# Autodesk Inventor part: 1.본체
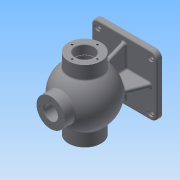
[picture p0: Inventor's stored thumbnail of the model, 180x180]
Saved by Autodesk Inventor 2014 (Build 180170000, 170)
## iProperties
Created: 2017-01
Part Number: 1.본체
Material: Generic
Document SubType Name: Modeling
Designer: ksu
Density: 1 g/cm^3
Appearance: Default
Author: ksu
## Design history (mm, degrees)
sketch "Sketch1"
  geometry: L1 (-62.5, 57.5)-(62.5, 57.5); L2 (62.5, 57.5)-(62.5, -57.5); L3 (62.5, -57.5)-(-62.5, -57.5); L4 (-62.5, -57.5)-(-62.5, 57.5); L5 (-62.5, 57.5)-(62.5, -57.5); L6 (62.5, 57.5)-(-62.5, -57.5); 1 further point
  constraints: 12 end point, 2 midpoint, 2 parallel, 1 horizontal, 1 perpendicular
  dimensions: "d0" = 125 distance of L2.end L3.end; "d1" = 115 distance of L1.end L2.end
extrude "Extrusion1" new body sketch "Sketch1" distance "d2" = 10; taper "d3" = 0 deg
fillet "Fillet1" dims "d4" = 12
fillet "Fillet2" dims "d5" = 3
sketch "Sketch2"
  geometry: A1 r 9 centre (-50.5, 45.5) between (-50.5, 54.5) and (-59.5, 45.5) reference; A2 r 9 centre (-50.5, -45.5) between (-59.5, -45.5) and (-50.5, -54.5) reference; A3 r 9 centre (50.5, -45.5) between (50.5, -54.5) and (59.5, -45.5) reference; A4 r 9 centre (50.5, 45.5) between (59.5, 45.5) and (50.5, 54.5) reference; 5 further points
  constraints: 4 coincident
hole "Hole1" sketch "Sketch2" at (-50.5, 45.5), (-50.5, -45.5), (50.5, -45.5), (50.5, 45.5) diameter "d6" = 8; stored, may be unused: countersink angle "d10" = 90 deg, drill point angle "d12" = 118 deg; dims "d7" = 6, "d8" = 12, "d9" = 3, "d11" = 8
sketch "Sketch3"
  geometry: L1 (-50.5, 0)-(50.5, 0) reference; L2 (0, 150.015)-(0, -20.474); L3 (0, 138)-(0, 32); A1 r 53 centre (0, 85) between (0, 138) and (0, 32); 1 further point
  constraints: 4 end point, 2 point on circle, 2 point on line, 1 centre point, 1 collinear, 1 perpendicular
  dimensions: "d13" = 106 diameter of A1; "d14" = 85 distance from line of L1 A1.centre
revolve "Revolution1" sketch "Sketch3" stored, may be unused: angle "d15" = 90 deg
sketch "Sketch4"
  geometry: L1 (-62.5, 7)-(-62.5, 0) reference; L2 (62.5, 0)-(62.5, 7) reference; L3 (-50.5, 0)-(50.5, 0) reference; C1 r 31 at (0, 85); 1 further point
  constraints: 1 centre point
  dimensions: "d16" = 125 distance between parallel lines of L1 L2 (derived); "d17" = 62 diameter of C1; "d18" = 85 distance from line of L3 C1.centre
extrude "Extrusion2" join sketch "Sketch4" stored distance "d19" = 136; taper "d20" = 0 deg
workplane "Work Plane1"
sketch "Sketch5"
  geometry: C1 r 27 at (0, 0); 1 further point
  constraints: 1 centre point, 1 coincident
  dimensions: "d22" = 54 diameter of C1
extrude "Extrusion3" join sketch "Sketch5" distance "d23" = 65; taper "d24" = 0 deg
sketch "Sketch6"
  geometry: L1 (-59.5, 10)-(-50.5, 10) reference; L2 (50.5, 10)-(-50.5, 10) reference; L3 (50.5, 10)-(59.5, 10) reference; L4 (-50.5, 10)-(50.5, 10) reference; L5 (-52.5, 10)-(-35.28, 52.62); L6 (-62.5, 0)-(-62.5, 7) reference; L7 (52.5, 10)-(35.28, 52.62); L8 (62.5, 7)-(62.5, 0) reference; L9 (-35.28, 52.62)-(35.28, 52.62); L10 (-52.5, 10)-(52.5, 10); 1 further point
  constraints: 8 end point, 2 point on line, 1 collinear, 1 perpendicular
  dimensions: "d25" = 10 distance from line of L6 L5.start; "d26" = 22 deg angle of L6 L5; "d27" = 10 distance from line of L7.start L8; "d28" = 22 deg angle of L7 L8
extrude "Extrusion4" join sketch "Sketch6" stored distance "d29" = 8; taper "d30" = 0 deg
sketch "Sketch7"
  geometry: L1 (-45.5, 10)-(45.5, 10) reference; L2 (-51.5, 10)-(-39.5, 10) reference; L3 (-54.5, 10)-(-45.5, 10) reference; L4 (45.5, 10)-(54.5, 10) reference; L5 (-47.5, 10)-(-31.246, 50.23); L6 (-57.5, 0)-(-57.5, 7) reference; L7 (47.5, 10)-(31.246, 50.23); L8 (57.5, 7)-(57.5, 0) reference; L9 (-31.246, 50.23)-(31.246, 50.23); L10 (-47.5, 10)-(47.5, 10); A1 r 3 centre (-54.5, 7) between (-54.5, 10) and (-57.5, 7) reference; A2 r 3 centre (54.5, 7) between (57.5, 7) and (54.5, 10) reference; 1 further point
  constraints: 8 end point, 2 point on line, 1 collinear, 1 perpendicular
  dimensions: "d31" = 10 distance from line of L6 L5.start; "d32" = 22 deg angle of L6 L5; "d33" = 22 deg angle of L7 L8; "d34" = 10 distance from line of L8 L7.start
extrude "Extrusion5" join sketch "Sketch7" stored distance "d35" = 8; taper "d36" = 0 deg
fillet "Fillet3" dims "d37" = 3
fillet "Fillet4" dims "d38" = 3
fillet "Fillet5" dims "d39" = 3
sketch "Sketch8"
  geometry: L1 (-103.502, 85)-(116.5, 85); L2 (-43, 85)-(43, 85); A1 r 43 centre (0, 85) between (43, 85) and (-43, 85); 1 further point
  constraints: 4 end point, 3 point on line, 2 point on circle, 1 centre point, 1 collinear, 1 horizontal
  dimensions: "d40" = 85 distance from line of point (0, 0) L1; "d41" = 86 diameter of A1
revolve "Revolution2" sketch "Sketch8" stored, may be unused: angle "d42" = 90 deg
sketch "Sketch9"
  geometry: C1 r 31 at (0, 0) reference; C2 r 17.5 at (0, 0); 1 further point
  constraints: 1 centre point, 1 coincident
  dimensions: "d43" = 35 diameter of C2
extrude "Extrusion6" cut sketch "Sketch9" stored distance "d44" = 8; taper "d45" = 0 deg
sketch "Sketch10"
  geometry: L1 (68, 102.5)-(68, 67.5) reference; L2 (-76.217, 85)-(110.893, 85); L3 (52, 85)-(50.25, 85); L4 (50.25, 85)-(50.25, 66.5); L5 (50.25, 66.5)-(52, 66.5); L6 (52, 66.5)-(52, 85); 1 further point
  constraints: 10 end point, 2 parallel, 2 perpendicular, 1 horizontal, 1 point on line
  dimensions: "d46" = 85 distance from line of point (0, 0) L2; "d47" = 16 distance between parallel lines of L1 L6; "d48" = 37 diameter of L5 L2; "d49" = 1.75 distance between parallel lines of L4 L6
revolve "Revolution3" sketch "Sketch10" stored, may be unused: angle "d50" = 90 deg
chamfer "Chamfer1" distance "d51" = 1; stored, may be unused: second distance "d52" = 2, angle "d53" = 45 deg
sketch "Sketch11"
  geometry: C1 r 27 at (0, 0) reference; C2 r 13 at (0, 0)
  constraints: 1 centre point, 1 coincident
  dimensions: "d54" = 26 diameter of C2
extrude "Extrusion7" cut sketch "Sketch11" distance "d55" = 25; taper "d56" = 0 deg
fillet "Fillet6" dims "d57" = 3
chamfer "Chamfer2" distance "d58" = 1; stored, may be unused: second distance "d59" = 2, angle "d60" = 45 deg
sketch "Sketch12"
  geometry: C1 r 31 at (0, 0) reference; 2 further points
  dimensions: "d61" = 22.5 distance of point (0, 22.5) C1.centre
hole "Hole2" sketch "Sketch12" at (0, 22.5) diameter "d62" = 3.459; stored, may be unused: countersink angle "d66" = 90 deg, drill point angle "d68" = 118 deg; dims "d63" = 12, "d64" = 12, "d65" = 3, "d67" = 15
pattern_circular "Circular Pattern1" dims angle "d70" = 360 deg
sketch "Sketch13"
  geometry: C1 r 31 at (0, 0) reference; 2 further points
  dimensions: "d72" = 24 distance of point (0, -24) C1.centre
hole "Hole3" sketch "Sketch13" at (0, -24) diameter "d73" = 3.459; stored, may be unused: countersink angle "d77" = 90 deg, drill point angle "d79" = 118 deg; dims "d74" = 16, "d75" = 12, "d76" = 3, "d78" = 19
pattern_circular "Circular Pattern2" dims angle "d81" = 360 deg
sketch "Sketch14"
  geometry: L1 (143.002, 66.239)-(143.002, 24.761); L2 (143.002, 24.761)-(136.998, 24.761); L3 (136.998, 24.761)-(136.998, 66.239); L4 (136.998, 66.239)-(143.002, 66.239); L5 (143.002, 66.239)-(136.998, 24.761); L6 (143.002, 24.761)-(136.998, 66.239); L7 (150, 18.5)-(150, 72.5) reference; L8 (132.286, 72.5)-(132.286, 18.5) reference; L9 (132.286, 72.5)-(150, 72.5) reference; L10 (132.286, 18.5)-(150, 18.5) reference; 2 further points
  constraints: 4 end point, 1 midpoint, 2 other
  dimensions: "d83" = 27 distance from line of L9 point (140, 45.5); "d84" = 10 distance from line of L7 point (140, 45.5)
emboss "Emboss1" sketch "Sketch14" dims "d0" = 125, "d1" = 115, "d85" = 0.5, "d86" = 0
sketch "Sketch15"
  geometry: C1 r 27 at (0, 0) reference; 1 further point
  dimensions: "d87" = 20 distance of point (0, 20) C1.centre
hole "Hole4" sketch "Sketch15" at (0, 20) diameter "d88" = 3.459; stored, may be unused: countersink angle "d92" = 90 deg, drill point angle "d94" = 118 deg; dims "d89" = 9, "d90" = 12, "d91" = 3, "d93" = 11
pattern_circular "Circular Pattern3" dims angle "d96" = 360 deg
body "Solid1"
node "Projected Loop1"
other parameters: "d21" = -85
